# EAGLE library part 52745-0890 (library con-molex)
FFC/FPC-to-Board 0.50mm (.020") SMT Top Contact Right Angle, ZIF, Style Receptacle 52745 / 52435 Source: http://www.molex.com/product/ffc/52745.html
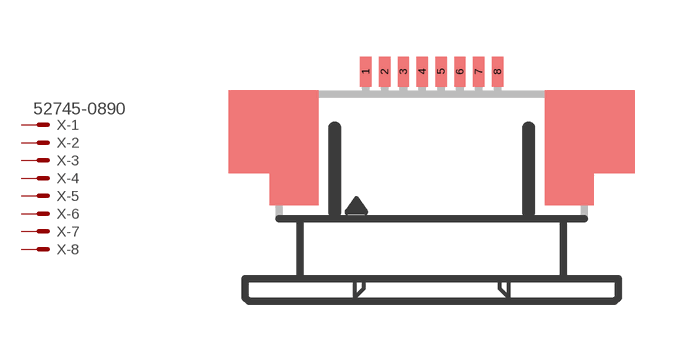
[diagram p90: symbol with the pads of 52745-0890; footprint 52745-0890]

Designator prefix X; gates -1=MV -2=M -3=M -4=M -5=M -6=M -7=M -8=M

## 52745-0890 (MPN: 52745-0890; OC_FARNELL: unknown; OC_NEWARK: 92M6377)  [52745-0890]
1  -1:S  pas
2  -2:S  pas
3  -3:S  pas
4  -4:S  pas
5  -5:S  pas
6  -6:S  pas
7  -7:S  pas
8  -8:S  pas

## Footprint 52745-0890 (pad centres in mm)
FFC/FPC-to-Board 0.50mm (.020") SMT Top Contact Right Angle, ZIF, Style Receptacle 52745 / 52435 Source: http://www.molex.com/product/ffc/52745.html
smd 0.3 x 0.8: 1 -1.75,2.5; 2 -1.25,2.5; 3 -0.75,2.5; 4 -0.25,2.5; 5 0.25,2.5; 6 0.75,2.5; 7 1.25,2.5; 8 1.75,2.5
